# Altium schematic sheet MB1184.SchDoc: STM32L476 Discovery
size A4; Date: 01-DEC-2013; Author: A.B; CompanyName: STMicroelectronics; Organization: Microcontrollers Division; Address1: 12, Rue Jules HOROWITZ; Address2: 38019 Grenoble; Address3: FRANCE; DocumentNumber: MB1184; Revision: C-01; SheetNumber: 1; SheetTotal: 10; Project: STM32L476G-DISCO
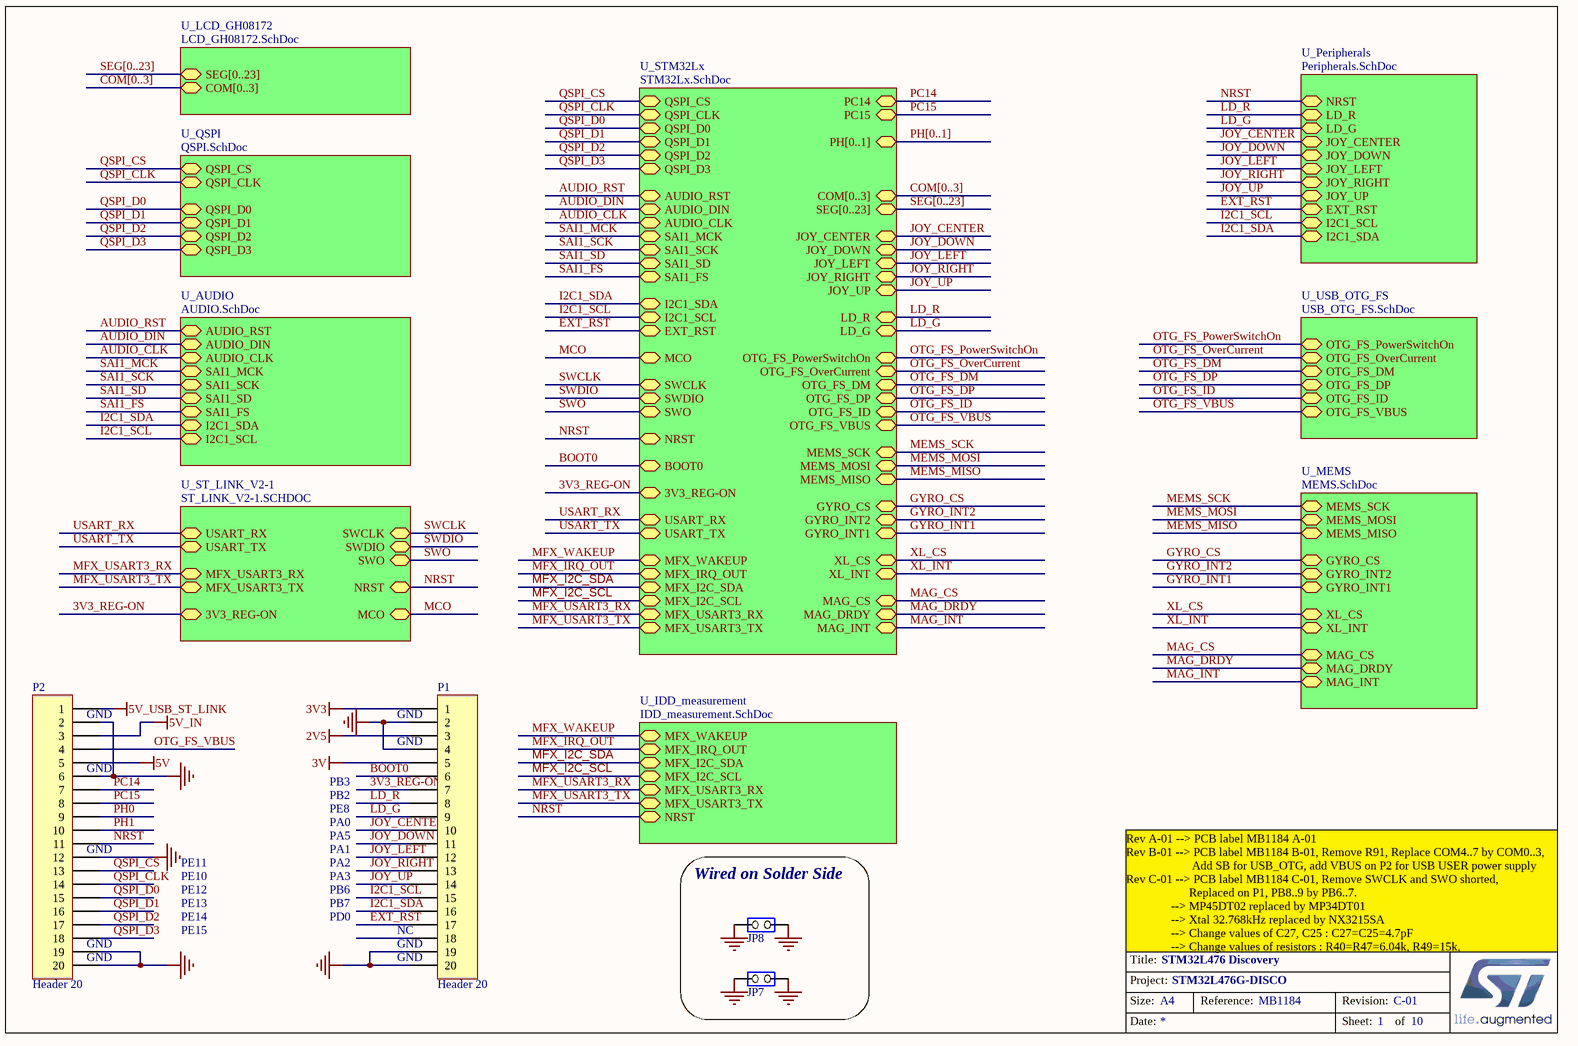
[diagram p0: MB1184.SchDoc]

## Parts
JP7  Jumper 2 pins  [SIP2/2.54]  (value not drawn)
JP8  Jumper 2 pins  [SIP2/2.54]  (value not drawn)
P1  Header 20  [HDR1X20]
P2  Header 20  [HDR1X20]

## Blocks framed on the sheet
Wired on Solder Side: JP7 JP8

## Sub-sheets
U_AUDIO = AUDIO.SchDoc: AUDIO_CLK, AUDIO_DIN, AUDIO_RST, SAI1_FS, SAI1_SD, SAI1_SCK, I2C1_SCL, I2C1_SDA, SAI1_MCK
U_IDD_measurement = IDD_measurement.SchDoc: MFX_WAKEUP, MFX_IRQ_OUT, MFX_I2C_SDA, MFX_I2C_SCL, MFX_USART3_RX, MFX_USART3_TX, NRST
U_LCD_GH08172 = LCD_GH08172.SchDoc: SEG[0..23], COM[0..3]
U_MEMS = MEMS.SchDoc: GYRO_CS, MAG_CS, MAG_INT, XL_INT, MAG_DRDY, MEMS_SCK, MEMS_MISO, MEMS_MOSI, GYRO_INT1, GYRO_INT2, XL_CS
U_Peripherals = Peripherals.SchDoc: NRST, LD_R, LD_G, EXT_RST, JOY_CENTER, JOY_DOWN, JOY_LEFT, JOY_RIGHT, JOY_UP, I2C1_SCL, I2C1_SDA
U_QSPI = QSPI.SchDoc: QSPI_D0, QSPI_D3, QSPI_D2 (bidir), QSPI_D1, QSPI_CLK, QSPI_CS
U_ST_LINK_V2-1 = ST_LINK_V2-1.SCHDOC: SWDIO, SWCLK, MCO, NRST, USART_RX, USART_TX, MFX_USART3_RX, MFX_USART3_TX, SWO, 3V3_REG-ON
U_STM32Lx = STM32Lx.SchDoc: NRST, MCO, LD_R, SWCLK, SWDIO, USART_TX, USART_RX, LD_G, MFX_IRQ_OUT, MFX_WAKEUP, QSPI_D0, QSPI_D3, QSPI_D2 (bidir), QSPI_D1, QSPI_CLK, QSPI_CS, SAI1_FS, SAI1_SD, SAI1_SCK, I2C1_SCL, I2C1_SDA, AUDIO_RST, SAI1_MCK, AUDIO_DIN, AUDIO_CLK, OTG_FS_PowerSwitchOn, OTG_FS_DM, OTG_FS_DP, OTG_FS_ID, OTG_FS_VBUS, OTG_FS_OverCurrent, SEG[0..23], COM[0..3], EXT_RST, PH[0..1], JOY_CENTER, JOY_DOWN, JOY_LEFT, JOY_RIGHT, JOY_UP, MEMS_SCK, MEMS_MISO, MEMS_MOSI, GYRO_CS, GYRO_INT1, GYRO_INT2, XL_CS, XL_INT, MAG_CS, MAG_DRDY, MAG_INT, MFX_USART3_RX, MFX_USART3_TX, MFX_I2C_SDA, MFX_I2C_SCL, BOOT0, SWO, 3V3_REG-ON, PC14, PC15
U_USB_OTG_FS = USB_OTG_FS.SchDoc: OTG_FS_PowerSwitchOn, OTG_FS_OverCurrent, OTG_FS_DM, OTG_FS_DP, OTG_FS_ID, OTG_FS_VBUS

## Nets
2V5: P1.3
3V: P1.5
3V3: P1.1
5V: P2.5
5V_IN: P2.3
5V_USB_ST_LINK: P2.1
GND: JP7.1(COMMON) JP7.2(NO) JP8.1(COMMON) JP8.2(NO) P1.2 P1.4 P1.19 P1.20 P2.2 P2.6 P2.12 P2.19 P2.20
3V3_REG-ON: P1.7 ; sheet U_STM32Lx/3V3_REG-ON, sheet U_ST_LINK_V2-1/3V3_REG-ON
AUDIO_CLK: sheet U_STM32Lx/AUDIO_CLK, sheet U_AUDIO/AUDIO_CLK
AUDIO_DIN: sheet U_STM32Lx/AUDIO_DIN, sheet U_AUDIO/AUDIO_DIN
AUDIO_RST: sheet U_STM32Lx/AUDIO_RST, sheet U_AUDIO/AUDIO_RST
BOOT0: P1.6 ; sheet U_STM32Lx/BOOT0
EXT_RST: P1.17 ; sheet U_STM32Lx/EXT_RST, sheet U_Peripherals/EXT_RST
GYRO_CS: sheet U_STM32Lx/GYRO_CS, sheet U_MEMS/GYRO_CS
GYRO_INT1: sheet U_STM32Lx/GYRO_INT1, sheet U_MEMS/GYRO_INT1
GYRO_INT2: sheet U_STM32Lx/GYRO_INT2, sheet U_MEMS/GYRO_INT2
I2C1_SCL: P1.15 ; sheet U_STM32Lx/I2C1_SCL, sheet U_AUDIO/I2C1_SCL, sheet U_Peripherals/I2C1_SCL
I2C1_SDA: P1.16 ; sheet U_STM32Lx/I2C1_SDA, sheet U_AUDIO/I2C1_SDA, sheet U_Peripherals/I2C1_SDA
JOY_CENTER: P1.10 ; sheet U_STM32Lx/JOY_CENTER, sheet U_Peripherals/JOY_CENTER
JOY_DOWN: P1.11 ; sheet U_STM32Lx/JOY_DOWN, sheet U_Peripherals/JOY_DOWN
JOY_LEFT: P1.12 ; sheet U_STM32Lx/JOY_LEFT, sheet U_Peripherals/JOY_LEFT
JOY_RIGHT: P1.13 ; sheet U_STM32Lx/JOY_RIGHT, sheet U_Peripherals/JOY_RIGHT
JOY_UP: P1.14 ; sheet U_STM32Lx/JOY_UP, sheet U_Peripherals/JOY_UP
LD_G: P1.9 ; sheet U_STM32Lx/LD_G, sheet U_Peripherals/LD_G
LD_R: P1.8 ; sheet U_STM32Lx/LD_R, sheet U_Peripherals/LD_R
MAG_CS: sheet U_STM32Lx/MAG_CS, sheet U_MEMS/MAG_CS
MAG_DRDY: sheet U_STM32Lx/MAG_DRDY, sheet U_MEMS/MAG_DRDY
MAG_INT: sheet U_STM32Lx/MAG_INT, sheet U_MEMS/MAG_INT
MCO: sheet U_STM32Lx/MCO, sheet U_ST_LINK_V2-1/MCO
MEMS_MISO: sheet U_STM32Lx/MEMS_MISO, sheet U_MEMS/MEMS_MISO
MEMS_MOSI: sheet U_STM32Lx/MEMS_MOSI, sheet U_MEMS/MEMS_MOSI
MEMS_SCK: sheet U_STM32Lx/MEMS_SCK, sheet U_MEMS/MEMS_SCK
MFX_I2C_SCL: sheet U_STM32Lx/MFX_I2C_SCL, sheet U_IDD_measurement/MFX_I2C_SCL
MFX_I2C_SDA: sheet U_STM32Lx/MFX_I2C_SDA, sheet U_IDD_measurement/MFX_I2C_SDA
MFX_IRQ_OUT: sheet U_STM32Lx/MFX_IRQ_OUT, sheet U_IDD_measurement/MFX_IRQ_OUT
MFX_USART3_RX: sheet U_STM32Lx/MFX_USART3_RX, sheet U_ST_LINK_V2-1/MFX_USART3_RX, sheet U_IDD_measurement/MFX_USART3_RX
MFX_USART3_TX: sheet U_STM32Lx/MFX_USART3_TX, sheet U_ST_LINK_V2-1/MFX_USART3_TX, sheet U_IDD_measurement/MFX_USART3_TX
MFX_WAKEUP: sheet U_STM32Lx/MFX_WAKEUP, sheet U_IDD_measurement/MFX_WAKEUP
NRST: P2.11 ; sheet U_STM32Lx/NRST, sheet U_ST_LINK_V2-1/NRST, sheet U_IDD_measurement/NRST, sheet U_Peripherals/NRST
OTG_FS_DM: sheet U_STM32Lx/OTG_FS_DM, sheet U_USB_OTG_FS/OTG_FS_DM
OTG_FS_DP: sheet U_STM32Lx/OTG_FS_DP, sheet U_USB_OTG_FS/OTG_FS_DP
OTG_FS_ID: sheet U_STM32Lx/OTG_FS_ID, sheet U_USB_OTG_FS/OTG_FS_ID
OTG_FS_OverCurrent: sheet U_STM32Lx/OTG_FS_OverCurrent, sheet U_USB_OTG_FS/OTG_FS_OverCurrent
OTG_FS_PowerSwitchOn: sheet U_STM32Lx/OTG_FS_PowerSwitchOn, sheet U_USB_OTG_FS/OTG_FS_PowerSwitchOn
OTG_FS_VBUS: P2.4 ; sheet U_STM32Lx/OTG_FS_VBUS, sheet U_USB_OTG_FS/OTG_FS_VBUS
PC14: P2.7 ; sheet U_STM32Lx/PC14
PC15: P2.8 ; sheet U_STM32Lx/PC15
PH0: P2.9
PH1: P2.10
QSPI_CLK: P2.14 ; sheet U_STM32Lx/QSPI_CLK, sheet U_QSPI/QSPI_CLK
QSPI_CS: P2.13 ; sheet U_STM32Lx/QSPI_CS, sheet U_QSPI/QSPI_CS
QSPI_D0: P2.15 ; sheet U_STM32Lx/QSPI_D0, sheet U_QSPI/QSPI_D0
QSPI_D1: P2.16 ; sheet U_STM32Lx/QSPI_D1, sheet U_QSPI/QSPI_D1
QSPI_D2: P2.17 ; sheet U_STM32Lx/QSPI_D2, sheet U_QSPI/QSPI_D2
QSPI_D3: P2.18 ; sheet U_STM32Lx/QSPI_D3, sheet U_QSPI/QSPI_D3
SAI1_FS: sheet U_STM32Lx/SAI1_FS, sheet U_AUDIO/SAI1_FS
SAI1_MCK: sheet U_STM32Lx/SAI1_MCK, sheet U_AUDIO/SAI1_MCK
SAI1_SCK: sheet U_STM32Lx/SAI1_SCK, sheet U_AUDIO/SAI1_SCK
SAI1_SD: sheet U_STM32Lx/SAI1_SD, sheet U_AUDIO/SAI1_SD
SWCLK: sheet U_STM32Lx/SWCLK, sheet U_ST_LINK_V2-1/SWCLK
SWDIO: sheet U_STM32Lx/SWDIO, sheet U_ST_LINK_V2-1/SWDIO
SWO: sheet U_STM32Lx/SWO, sheet U_ST_LINK_V2-1/SWO
USART_RX: sheet U_STM32Lx/USART_RX, sheet U_ST_LINK_V2-1/USART_RX
USART_TX: sheet U_STM32Lx/USART_TX, sheet U_ST_LINK_V2-1/USART_TX
XL_CS: sheet U_STM32Lx/XL_CS, sheet U_MEMS/XL_CS
XL_INT: sheet U_STM32Lx/XL_INT, sheet U_MEMS/XL_INT

Not connected (* = marked no-connect by the designer): P1 18

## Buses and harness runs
bus COM[0..3] = sheet U_LCD_GH08172/COM[0..3]
bus COM[0..3] = sheet U_STM32Lx/COM[0..3]
bus PH[0..1] = sheet U_STM32Lx/PH[0..1]
bus SEG[0..23] = sheet U_LCD_GH08172/SEG[0..23]
bus SEG[0..23] = sheet U_STM32Lx/SEG[0..23]

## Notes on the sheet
- (near P2) GND
- (near P1) GND
- PB3
- PB2
- PE8
- PA0
- PA5
- PA1
- PE11
- PE10
- PE12
- PE13
- PE14
- PA2
- PA3
- PB6
- PB7
- PD0
- PE15
- (near P1) NC
- Rev A-01 --> PCB label MB1184 A-01
  Rev B-01 --> PCB label MB1184 B-01, Remove R91, Replace COM4..7 by COM0..3,
  Add SB for USB_OTG, add VBUS on P2 for USB USER power supply
  Rev C-01 --> PCB label MB1184 C-01, Remove SWCLK and SWO shorted,
  Replaced on P1, PB8..9 by PB6..7.
  --> MP45DT02 replaced by MP34DT01
  --> Xtal 32.768kHz replaced by NX3215SA
  --> Change values of C27, C25 : C27=C25=4.7pF
  --> Change values of resistors : R40=R47=6.04k, R49=15k, R48=R42=R50=300k

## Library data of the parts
JP7 JP8 = Jumper2
P1 P2 = Header 20: Header, 20-Pin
